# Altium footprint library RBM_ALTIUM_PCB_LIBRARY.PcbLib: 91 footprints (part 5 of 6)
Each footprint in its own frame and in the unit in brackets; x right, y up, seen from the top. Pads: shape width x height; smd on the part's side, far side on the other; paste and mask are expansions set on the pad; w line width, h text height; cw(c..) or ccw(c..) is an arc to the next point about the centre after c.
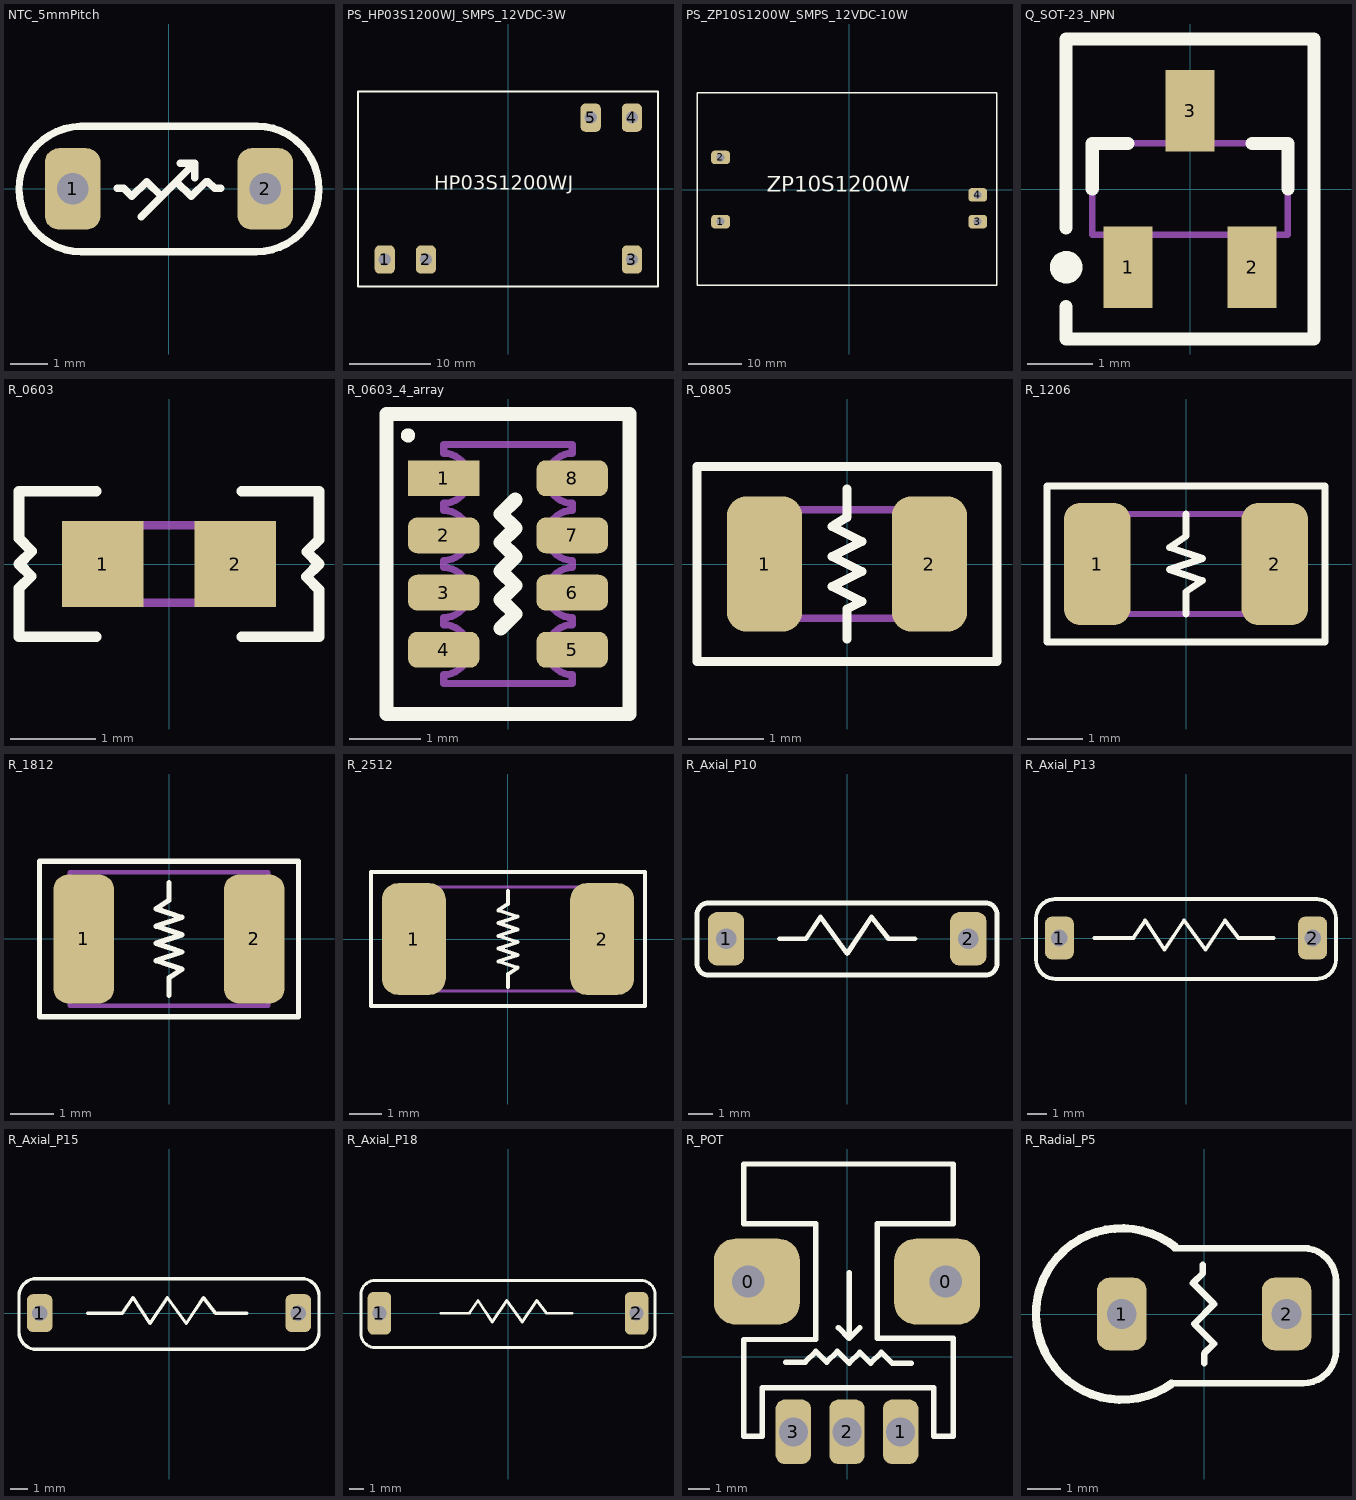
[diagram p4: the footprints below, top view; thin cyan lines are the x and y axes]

## NTC_5mmPitch [mm]
pads (2):
  rrect50% 1.5x2.2 hole 0.85: 1(-2.6,0) 2(2.6,0)
Top Overlay:
  lines w0.1: -1.229,0.018 -1.218,0.018 ; 1,0.2 1.049,0.2 ; -0.6,0.2 -0.6,0.2 ; 0.6,-0.2 0.6,-0.2
  lines w0.2: -2.384,1.691 ccw(c-2.353,-0.005) -2.371,-1.7 ; -2.384,1.692 2.38,1.692 ; -2.353,-1.694 2.355,-1.694 ; -1.4,0.018 -1.229,0.018 ; -1.218,0.018 -1,-0.2 -0.6,0.2 -0.2,-0.2 0.2,0.2 0.6,-0.2 1,0.2 ; -0.75,-0.75 0.7,0.7 ; 0.3,0.7 0.7,0.7 ; 0.7,0.3 0.7,0.7 ; 1.049,0.2 1.232,0.018 1.4,0.018 ; 2.347,-1.694 ccw(c2.355,0.002) 2.38,1.698
3D body: height 4, standoff 1, extent 2.302,-0.299 2.9,0.3
3D body: height 4, standoff 1, extent -2.9,-0.3 -2.302,0.299
3D body: height 6.75, standoff 1.25, extent -2.752,-1.638 2.748,1.692
3D body: height 2, standoff -1, extent 2.327,-0.274 2.875,0.275
3D body: height 2, standoff -1, extent -2.874,-0.274 -2.326,0.274

## PS_HP03S1200WJ_SMPS_12VDC-3W [mm]
pads (5):
  rrect50% 2.5x3.5 hole 1.5: 1(-15.24,-8.75) 2(-10.16,-8.75) 3(15.24,-8.75) 4(15.24,8.75) 5(10.16,8.75)
Top Overlay:
  lines w0.254: -18.54,-12.05 18.46,-12.05 18.46,11.95 -18.54,11.95 -18.54,-12.05
  text "HP03S1200WJ" at -9.14,-0.75 h3
Bottom Overlay:
  lines w0.254: -18.54,-12.05 18.46,-12.05 18.46,11.95 -18.54,11.95 -18.54,-12.05
  text "L" at -14.24,-6.05 h3
  text "N" at -9.04,-6.05 h3
  text "V" at 11.36,4.15 h3
  text "G" at 16.31,4.1 h3
3D body: height 6, standoff -4, extent -10.656,-9.249 -9.66,-8.251
3D body: height 6, standoff -4, extent -15.736,-9.249 -14.74,-8.251
3D body: height 6, standoff -4, extent 14.744,-9.249 15.74,-8.251
3D body: height 6, standoff -4, extent 14.744,8.251 15.74,9.249
3D body: height 15.5, standoff 0, extent -18.54,-12.05 18.36,11.95
3D body: height 6, standoff -4, extent 9.664,8.251 10.66,9.249

## PS_ZP10S1200W_SMPS_12VDC-10W [mm]
pads (4):
  rrect50% 3.5x2.5 hole 1.5: 1(-24,-6) 2(-24,6) 3(24,-6) 4(24,-1)
Top Overlay:
  lines w0.254: -28.4,-17.9 27.6,-17.9 27.6,18.1 -28.4,18.1 -28.4,-17.9
  text "ZP10S1200W" at -15.4,-1.4 h5
Bottom Overlay:
  lines w0.254: -28.4,-17.9 27.6,-17.9 27.6,18.1 -28.4,18.1 -28.4,-17.9
  text "L" at -17.9,-6.7 h3
  text "N" at -18,5 h3
  text "+Ve" at 20.4,-7 h3
  text "-Ve" at 20.3,-1.7 h3
3D body: height 21, standoff -4, extent -24.496,5.501 -23.5,6.499
3D body: height 21, standoff -4, extent -24.496,-6.499 -23.5,-5.501
3D body: height 21, standoff -4, extent 23.504,-1.499 24.5,-0.501
3D body: height 21, standoff -4, extent 23.504,-6.499 24.5,-5.501
3D body: height 25, standoff 0, extent -28.4,-17.9 27.6,18.1

## Q_SOT-23_NPN [mm] "NPN 200mA 40V 250mW SOT-23(SOT-23-3)"
height 1.15
pads (3):
  rect 0.75x1.25 smd: 1(-0.95,-1.2) 2(0.95,-1.2) 3(0,1.2)
Top Overlay:
  circle w0.25: c-1.9,-1.2 r0.125
  lines w0.2: -1.9,-1.8 -1.9,-2.3 1.9,-2.3 1.9,2.3 -1.9,2.3 -1.9,-0.6 ; -1.5,0 -1.5,0.7 -0.95,0.7 ; 0.95,0.7 1.5,0.7 1.5,0
Mechanical 13:
  lines w0.1: -1.5,-0.7 -1.5,0.7 1.5,0.7 1.5,-0.7 -1.5,-0.7
3D body "SOT95P245X115-3N.step": height 1.15, standoff 0, extent -1.5,-1.3 1.5,1.3

## R_0603 [mm] "RK73G1JTTD1000F; 0603 Chip Resistor - Surface Mount RoHS"
height 0.55
pads (2):
  rect 0.95x1 smd: 1(-0.775,0) 2(0.775,0)
Top Overlay:
  lines w0.125: -1.75,-0.85 -1.75,-0.286 ; -1.75,-0.283 -1.609,-0.141 -1.75,0 -1.6,0.15 -1.75,0.3 -1.75,0.85 -0.85,0.85 ; -1.746,-0.85 -0.85,-0.85 ; 0.85,-0.85 1.75,-0.85 1.75,-0.3 1.6,-0.15 1.75,0 1.609,0.141 1.75,0.283 ; 0.85,0.85 1.746,0.85 ; 1.75,0.286 1.75,0.85
Assembly Top:
  lines w0.1: -0.9,-0.45 -0.9,0.45 0.9,0.45 0.9,-0.45 -0.9,-0.45
3D body "R_0603.step": height 0.55, standoff 0, extent -0.9,-0.45 0.9,0.45

## R_0603_4_array [mm] "Chip Array, Concave, 8-Leads, Pitch 0.80mm,  Body 3.20x1.60mm,  IPC Medium Density"
height 0.7
pads (8):
  rect 1x0.5 smd: 1(-0.9,1.2)
  rrect50% 1x0.5 smd: 2(-0.9,0.4) 3(-0.9,-0.4) 4(-0.9,-1.2) 5(0.9,-1.2) 6(0.9,-0.4) 7(0.9,0.4) 8(0.9,1.2)
Top Overlay:
  circle w0.1: c-1.4,1.8 r0.05
  lines w0.2: -0.1,-0.9 0.1,-0.7 -0.1,-0.5 0.1,-0.3 -0.1,-0.1 0.1,0.1 -0.1,0.3 0.1,0.5 -0.1,0.7 0.1,0.9 ; -1.7,-2.1 -1.7,2.1 1.7,2.1 1.7,-2.1 -1.7,-2.1
Mechanical 13:
  lines w0.1: -0.9,-1.675 -0.9,-1.55 ccw(c-0.9,-1.2) -0.9,-0.85 -0.9,-0.75 ccw(c-0.9,-0.4) -0.9,-0.05 -0.9,0.05 ccw(c-0.9,0.4) -0.9,0.75 -0.9,0.85 ccw(c-0.9,1.2) -0.9,1.55 -0.9,1.675 0.9,1.675 0.9,1.55 ccw(c0.9,1.2) 0.9,0.85 0.9,0.75 ccw(c0.9,0.4) 0.9,0.05 0.9,-0.05 ccw(c0.9,-0.4) 0.9,-0.75 0.9,-0.85 ccw(c0.9,-1.2) 0.9,-1.55 0.9,-1.675 -0.9,-1.675
3D body "R_0603_4_array.step": height 0.7, standoff 0, extent -0.95,-1.675 0.95,1.675

## R_0805 [mm]
height 0.65
pads (2):
  rrect50% 1x1.8 smd: 1(-1.1,0) 2(1.1,0)
Top Overlay:
  lines w0.125: 0,-1 0,-0.6 0.2,-0.5 -0.2,-0.3 0.2,-0.1 -0.2,0.1 0.2,0.3 -0.2,0.5 0,0.625 0,1 ; -2,-1.3 2,-1.3 2,1.3 -2,1.3 -2,-1.3
Mechanical 13:
  lines w0.1: -1.1,-0.725 -1.1,0.725 1.1,0.725 1.1,-0.725 -1.1,-0.725
3D body "R_0805.step": height 0.65, standoff 0, extent -1.1,-0.725 1.1,0.725

## R_1206 [mm]
height 0.65
pads (2):
  rrect50% 1.2x2.2 smd: 1(-1.6,0) 2(1.6,0)
Top Overlay:
  lines w0.125: 0,-0.9 0,-0.5 0.3,-0.3 -0.3,-0.1 0.3,0.1 -0.3,0.3 0,0.5 0,0.9 ; -2.5,-1.4 -2.5,1.4 2.5,1.4 2.5,-1.4 -2.5,-1.4
Mechanical 13:
  lines w0.1: -1.65,-0.9 1.65,-0.9 1.65,0.9 -1.65,0.9 -1.65,-0.9
3D body "R_1206.step": height 0.65, standoff 0, extent -1.65,-0.9 1.65,0.9

## R_1812 [mm] "Chip Resistor, 2-Leads, Body 4.50x3.00mm, IPC Medium Density"
height 0.6
pads (2):
  rrect50% 1.4x3 smd: 1(-1.975,0) 2(1.975,0)
Top Overlay:
  lines w0.125: 0,-1.3 0,-0.9 0.3,-0.7 -0.3,-0.5 0.3,-0.3 -0.3,-0.1 0.3,0.1 -0.3,0.3 0.3,0.5 -0.3,0.7 0,0.9 0,1.3 ; -3,-1.8 -3,1.8 3,1.8 3,-1.8 -3,-1.8
Assembly Top:
  lines w0.1: -2.3,-1.55 2.3,-1.55 2.3,1.55 -2.3,1.55 -2.3,-1.55
3D body "RESC4530X06N.step": height 0.6, standoff 0, extent -2.3,-1.55 2.3,1.55

## R_2512 [mm] "Chip Resistor, 2-Leads, Body 6.35x3.10mm, IPC Medium Density"
height 0.65
pads (2):
  rrect50% 2x3.5 smd: 1(-2.95,0) 2(2.95,0)
Top Overlay:
  lines w0.125: 0,-1.5 0,-1.1 0.3,-0.9 -0.3,-0.7 0.3,-0.5 -0.3,-0.3 0.3,-0.1 -0.3,0.1 0.3,0.3 -0.3,0.5 0.3,0.7 -0.3,0.9 0,1.1 0,1.5 ; -4.3,-2.1 4.3,-2.1 4.3,2.1 -4.3,2.1 -4.3,-2.1
Mechanical 13:
  lines w0.1: -3.275,-1.625 3.275,-1.625 3.275,1.625 -3.275,1.625 -3.275,-1.625
3D body "R_2512.step": height 0.65, standoff 0, extent -3.275,-1.625 3.275,1.625

## R_Axial_P10 [mm] "Resistors 7mm Length"
pads (2):
  rrect50% 1.5x2.2 hole 0.85: 1(-5,0) 2(5,0)
Top Overlay:
  lines w0.2: -2.8,0 -1.7,0 -1.1,0.9 0,-0.6 1,0.9 1.7,0 2.8,0 ; -6.2,-1.017 ccw(c-5.717,-1.017) -5.717,-1.5 5.7,-1.5 ccw(c5.7,-1.017) 6.183,-1.017 6.183,1 ccw(c5.7,1) 5.7,1.483 -5.717,1.483 ccw(c-5.717,1) -6.2,1 -6.2,-1.017
3D body "User Library-Res40-Axial 0_25W-2_2R.step": height 2.41, standoff -2, extent -5.38,-1.2 5.38,1.2

## R_Axial_P13 [mm] "Resistors 10.5mm Length"
pads (2):
  rrect50% 1.5x2.2 hole 0.85: 1(-6.5,0) 2(6.5,0)
Top Overlay:
  lines w0.2: -6.725,2 6.725,2 ; -6.7,2 ccw(c-6.7,1) -7.7,1 -7.7,-1.1 ccw(c-6.7,-1.1) -6.7,-2.1 6.725,-2.1 ; -4.7,0 -2.7,0 -2.1,0.9 -1.1,-0.6 -0.1,0.9 1,-0.6 2,0.9 2.7,0 4.5,0 ; 6.7,-2.1 ccw(c6.7,-1.1) 7.7,-1.1 7.7,1 ccw(c6.7,1) 6.7,2
3D body "User Library-Res50-Axial 0_5W-2_2K.step": height 5.87, standoff -3.5, extent -6.725,-1.875 6.725,1.875

## R_Axial_P15 [mm] "Resistors 12mm Length"
pads (2):
  rrect50% 1.5x2.2 hole 0.9: 1(-7.5,0) 2(7.5,0)
Top Overlay:
  lines w0.2: -4.7,0 -2.7,0 -2.1,0.9 -1.1,-0.6 -0.1,0.9 1,-0.6 2,0.9 2.7,0 4.5,0 ; -8.7,-1.1 ccw(c-7.7,-1.1) -7.7,-2.1 7.7,-2.1 ccw(c7.7,-1.1) 8.7,-1.1 8.7,1 ccw(c7.7,1) 7.7,2 -7.7,2 ccw(c-7.7,1) -8.7,1 -8.7,-1.1
3D body "User Library-Res50-Axial 0_5W-2_2K.step": height 5.87, standoff -3.5, extent -6.725,-1.875 6.725,1.875

## R_Axial_P18 [mm] "220 ohm 2W 5%"
pads (2):
  rrect50% 1.65x3 hole 1: 1(-9,0) 2(9,0)
Top Overlay:
  lines w0.2: -4.7,0 -2.7,0 -2.1,0.9 -1.1,-0.6 -0.1,0.9 1,-0.6 2,0.9 2.7,0 4.5,0 ; -10.3,-1.4 ccw(c-9.3,-1.4) -9.3,-2.4 9.3,-2.4 ccw(c9.3,-1.4) 10.3,-1.4 10.3,1.3 ccw(c9.3,1.3) 9.3,2.3 -9.3,2.3 ccw(c-9.3,1.3) -10.3,1.3 -10.3,-1.4

## R_POT [mm]
pads (5):
  rrect50% 4x4 hole 1.5 square copper offset 0.4,0: 0(-4.6,3.5)
  rrect50% 4x4 hole 1.5 square copper offset -0.4,0: 0(4.6,3.5)
  rrect50% 1.65x3 hole 1.35: 1(2.5,-3.5) 2(0,-3.5) 3(-2.5,-3.5)
Top Overlay:
  lines w0.254: -2.85,-0.25 -1.95,-0.25 -1.45,0.25 ; -0.4,1.35 0.1,0.85 ; 0.05,-0.25 -0.45,0.25 ; 0.1,3.9 0.1,0.85 ; 0.6,1.35 0.1,0.85 ; 3,-0.3 2.1,-0.3 1.6,0.2 1.1,-0.3 ; -1.45,0.25 -0.95,-0.25 -0.45,0.25 ; -1.45,0.25 -1.45,0.25 ; -0.45,0.25 -0.45,0.25 ; 0.1,-0.3 0.6,0.2 1.1,-0.3 ; 0.1,-0.3 0.1,-0.3 ; 1.1,-0.3 1.1,-0.3 ; -4.8,-3.7 -3.95,-3.7 -3.95,-1.45 4.05,-1.45 4.05,-3.7 4.952,-3.7 4.952,0.85 1.4,0.85 1.4,6.2 4.952,6.2 4.952,8.975 -4.8,8.975 -4.8,6.2 -1.45,6.2 -1.45,0.8 -4.8,0.8 -4.8,-3.7
3D body "SW3dPS-Potentiometer 250U.STEP": height 15.26, standoff -3.8, extent -4.876,-3.8 4.876,8.75

## R_Radial_P5 [mm] "All Through Hole Resistors"
pads (2):
  rrect50% 1.5x2.2 hole 0.9: 1(-2.5,0) 2(2.5,0)
Top Overlay:
  lines w0.2: -1,-2.1 3,-2.1 ccw(c3,-1.1) 4,-1.1 4,1 ccw(c3,1) 3,2 -0.9,2 ; -0.038,1.5 -0.038,1.238 -0.337,0.938 0.3,0.3 ; 0,-1.5 0,-1.2 0.3,-0.9 -0.3,-0.3 ; -0.3,-0.3 -0.3,-0.3 ; -0.3,-0.3 0.3,0.3 ; 0.3,0.3 0.3,0.3
  lines w0.254: -0.989,-2.116 cw(c-2.5,0) -0.876,2.03
3D body "Res_Radial_5mmP.STEP": height 15.25, standoff -3, extent -5,-2.5 2.75,2.5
